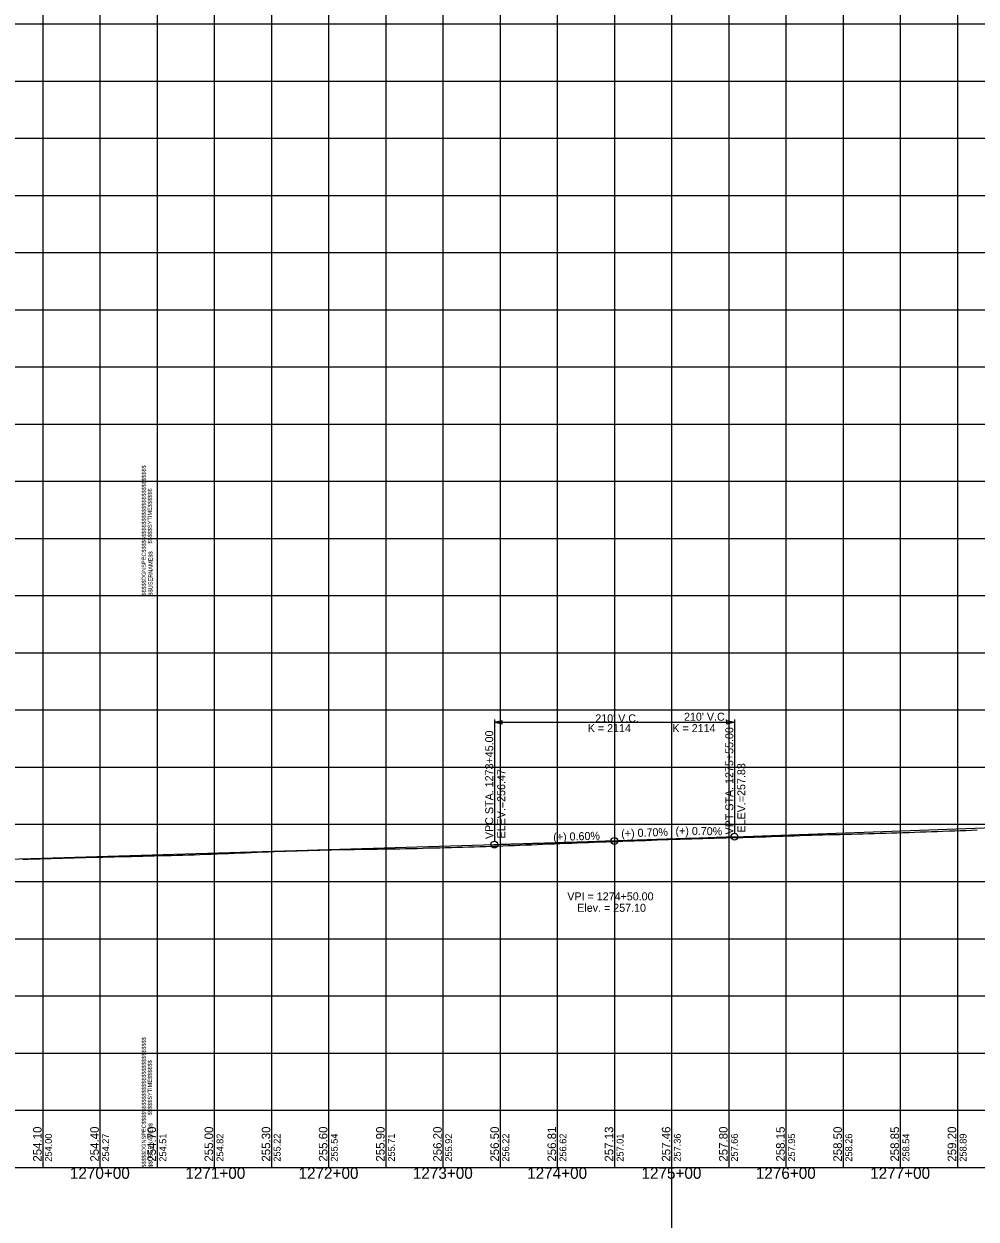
# Model space of a CAD drawing. Extents: x -90830 to 2015517, y -20856 to 836331.
# Drawn here: x 15857 to 16690, y -19432 to -18387 of the extents above; entities that cross this region are included whole.
import ezdxf

# ---------------------------------------------------------------- set-up
doc = ezdxf.new("R2010")
doc.units = 0
for name, color, linetype in [('Level 1', 7, 'Continuous'), ('RD_DDB_GradeTX', 7, 'Continuous'), ('RD_DDB_Profile_Elev', 7, 'Continuous'), ('RD_DDB_Profile_EX', 7, 'Continuous'), ('RD_DDB_Profile_Lbl', 7, 'Continuous'), ('RD_DDB_Profile_PR', 7, 'Continuous'), ('RD_DDB_StaTX', 7, 'Continuous'), ('RD_DDB_StripGrade', 7, 'Continuous'), ('RD_DDB_VCLbl', 7, 'Continuous'), ('RD_GPK_Profile_Cell', 7, 'Continuous'), ('RD_TX_Drainage', 7, 'Continuous')]:
    doc.layers.add(name, color=color, linetype=linetype)

msp = doc.modelspace()

# ---------------------------------------------------------------- linework, layer by layer
at = {"layer": 'Level 1'}
for p, q in [((16423.5, -12693.4), (16423.5, -20856.1)), ((15873.5, -17886.5), (15873.5, -18386.5)), ((15923.5, -17886.5), (15923.5, -18386.5)), ((15973.5, -17886.5), (15973.5, -18386.5)), ((15973.5, -17886.5), (15973.5, -18386.5)), ((15973.5, -17886.5), (15973.5, -18386.5)), ((16023.5, -17886.5), (16023.5, -18386.5)), ((16073.5, -17886.5), (16073.5, -18386.5)), ((16123.5, -17886.5), (16123.5, -18386.5)), ((16173.5, -17886.5), (16173.5, -18386.5)), ((16223.5, -17886.5), (16223.5, -18386.5)), ((16273.5, -17886.5), (16273.5, -18386.5)), ((16323.5, -17886.5), (16323.5, -18386.5)), ((16373.5, -17886.5), (16373.5, -18386.5)), ((16423.5, -17886.5), (16423.5, -18386.5)), ((16473.5, -17886.5), (16473.5, -18386.5)), ((16523.5, -17886.5), (16523.5, -18386.5)), ((16573.5, -17886.5), (16573.5, -18386.5)), ((16623.5, -17886.5), (16623.5, -18386.5)), ((16673.5, -17886.5), (16673.5, -18386.5)), ((14373.5, -18386.5), (15973.5, -18386.5)), ((14373.5, -18386.5), (15973.5, -18386.5)), ((15873.5, -18386.5), (15873.5, -18886.5)), ((15923.5, -18386.5), (15923.5, -18886.5)), ((15973.5, -18386.5), (15973.5, -18886.5)), ((15973.5, -18386.5), (15973.5, -18886.5)), ((15973.5, -18386.5), (17573.5, -18386.5)), ((15973.5, -18386.5), (15973.5, -18886.5)), ((15973.5, -18386.5), (17573.5, -18386.5)), ((16023.5, -18386.5), (16023.5, -18886.5)), ((16073.5, -18386.5), (16073.5, -18886.5)), ((16123.5, -18386.5), (16123.5, -18886.5)), ((16173.5, -18386.5), (16173.5, -18886.5)), ((16223.5, -18386.5), (16223.5, -18886.5)), ((16273.5, -18386.5), (16273.5, -18886.5)), ((16323.5, -18386.5), (16323.5, -18886.5)), ((16373.5, -18386.5), (16373.5, -18886.5)), ((16423.5, -18386.5), (16423.5, -18886.5)), ((16473.5, -18386.5), (16473.5, -18886.5)), ((16523.5, -18386.5), (16523.5, -18886.5)), ((16573.5, -18386.5), (16573.5, -18886.5)), ((16623.5, -18386.5), (16623.5, -18886.5)), ((16673.5, -18386.5), (16673.5, -18886.5)), ((14373.5, -18436.5), (15973.5, -18436.5)), ((15973.5, -18436.5), (17573.5, -18436.5)), ((14373.5, -18486.5), (15973.5, -18486.5)), ((15973.5, -18486.5), (17573.5, -18486.5)), ((14373.5, -18536.5), (15973.5, -18536.5)), ((15973.5, -18536.5), (17573.5, -18536.5)), ((14373.5, -18586.5), (15973.5, -18586.5)), ((15973.5, -18586.5), (17573.5, -18586.5)), ((14373.5, -18636.5), (15973.5, -18636.5)), ((15973.5, -18636.5), (17573.5, -18636.5)), ((14373.5, -18686.5), (15973.5, -18686.5)), ((15973.5, -18686.5), (17573.5, -18686.5)), ((14373.5, -18736.5), (15973.5, -18736.5)), ((15973.5, -18736.5), (17573.5, -18736.5)), ((14373.5, -18786.5), (15973.5, -18786.5)), ((15973.5, -18786.5), (17573.5, -18786.5)), ((14373.5, -18836.5), (15973.5, -18836.5)), ((15973.5, -18836.5), (17573.5, -18836.5)), ((14373.5, -18886.5), (15973.5, -18886.5)), ((14373.5, -18886.5), (15973.5, -18886.5)), ((15873.5, -18886.5), (15873.5, -19386.5)), ((15923.5, -18886.5), (15923.5, -19386.5)), ((15973.5, -18886.5), (17573.5, -18886.5)), ((15973.5, -18886.5), (15973.5, -19386.5)), ((15973.5, -18886.5), (15973.5, -19386.5)), ((15973.5, -18886.5), (17573.5, -18886.5)), ((15973.5, -18886.5), (15973.5, -19386.5)), ((16023.5, -18886.5), (16023.5, -19386.5)), ((16073.5, -18886.5), (16073.5, -19386.5)), ((16123.5, -18886.5), (16123.5, -19386.5)), ((16173.5, -18886.5), (16173.5, -19386.5)), ((16223.5, -18886.5), (16223.5, -19386.5)), ((16273.5, -18886.5), (16273.5, -19386.5)), ((16323.5, -18886.5), (16323.5, -19386.5)), ((16373.5, -18886.5), (16373.5, -19386.5)), ((16423.5, -18886.5), (16423.5, -19386.5)), ((16473.5, -18886.5), (16473.5, -19386.5)), ((16523.5, -18886.5), (16523.5, -19386.5)), ((16573.5, -18886.5), (16573.5, -19386.5)), ((16623.5, -18886.5), (16623.5, -19386.5)), ((16673.5, -18886.5), (16673.5, -19386.5)), ((14373.5, -18936.5), (15973.5, -18936.5)), ((15973.5, -18936.5), (17573.5, -18936.5)), ((14373.5, -18986.5), (15973.5, -18986.5)), ((15973.5, -18986.5), (17573.5, -18986.5)), ((14373.5, -19036.5), (15973.5, -19036.5)), ((15973.5, -19036.5), (17573.5, -19036.5)), ((14373.5, -19086.5), (15973.5, -19086.5)), ((15973.5, -19086.5), (17573.5, -19086.5)), ((14373.5, -19136.5), (15973.5, -19136.5)), ((15973.5, -19136.5), (17573.5, -19136.5)), ((14373.5, -19186.5), (15973.5, -19186.5)), ((15973.5, -19186.5), (17573.5, -19186.5)), ((14373.5, -19236.5), (15973.5, -19236.5)), ((15973.5, -19236.5), (17573.5, -19236.5)), ((14373.5, -19286.5), (15973.5, -19286.5)), ((15973.5, -19286.5), (17573.5, -19286.5)), ((14373.5, -19336.5), (15973.5, -19336.5)), ((15973.5, -19336.5), (17573.5, -19336.5)), ((14373.5, -19386.5), (15973.5, -19386.5)), ((15973.5, -19386.5), (17573.5, -19386.5))]:
    msp.add_line(p, q, dxfattribs=at)
at = {"layer": 'RD_DDB_GradeTX'}
for p, q in [((16302.5, -19103.1), (16370.5, -19101.1)), ((16444.4, -19098.5), (16376.5, -19100.9))]:
    msp.add_line(p, q, dxfattribs=at)
msp.add_circle((16373.5, -19101), 3, dxfattribs=at)
at = {"layer": 'RD_DDB_Profile_EX'}
for points in [[(16045.9, -19111.5), (16050.9, -19111.3), (16055.9, -19111.1), (16060.9, -19110.9), (16065.9, -19110.7), (16070.9, -19110.5), (16075.9, -19110.3), (16080.9, -19110.1), (16085.9, -19110), (16090.9, -19109.8), (16095.9, -19109.6), (16100.9, -19109.5), (16105.9, -19109.3), (16110.9, -19109.2), (16115.9, -19109), (16120.9, -19108.9), (16125.9, -19108.8), (16130.9, -19108.6), (16135.9, -19108.5), (16140.9, -19108.4), (16145.9, -19108.4), (16150.9, -19108.3), (16155.9, -19108.2), (16160.9, -19108.1), (16165.9, -19108.1), (16170.9, -19108), (16175.9, -19107.9), (16180.9, -19107.9), (16185.9, -19107.8), (16190.9, -19107.7), (16195.9, -19107.6), (16200.9, -19107.5), (16205.9, -19107.3), (16210.9, -19107.2), (16215.9, -19107.1), (16220.9, -19107), (16225.9, -19106.8), (16230.9, -19106.7), (16235.9, -19106.6), (16240.9, -19106.5), (16245.9, -19106.3), (16250.9, -19106.2), (16255.9, -19106), (16260.9, -19105.8), (16265.9, -19105.7), (16270.9, -19105.5), (16275.9, -19105.3), (16280.9, -19105.1), (16285.9, -19104.9), (16290.9, -19104.7), (16295.9, -19104.5), (16300.9, -19104.3), (16305.9, -19104.1), (16310.9, -19103.9), (16315.9, -19103.7), (16320.9, -19103.5), (16325.9, -19103.3), (16330.9, -19103.1), (16335.9, -19102.9), (16340.9, -19102.7), (16345.9, -19102.5), (16350.9, -19102.3), (16355.9, -19102.1), (16360.9, -19101.9), (16365.9, -19101.7), (16370.9, -19101.5), (16375.9, -19101.4), (16380.9, -19101.2), (16385.9, -19101), (16390.9, -19100.8), (16395.9, -19100.6), (16400.9, -19100.5), (16405.9, -19100.3), (16410.9, -19100.1), (16415.9, -19099.9), (16420.9, -19099.8), (16425.9, -19099.6), (16430.9, -19099.4), (16435.9, -19099.3), (16440.9, -19099.1), (16445.9, -19098.9), (16450.9, -19098.8), (16455.9, -19098.6), (16460.9, -19098.5), (16465.9, -19098.4), (16470.9, -19098.3), (16475.9, -19098.1), (16480.9, -19098), (16485.9, -19097.9), (16490.9, -19097.8), (16495.9, -19097.6), (16500.9, -19097.5), (16505.9, -19097.3), (16510.9, -19097.2), (16515.9, -19097), (16520.9, -19096.8), (16525.9, -19096.7), (16530.9, -19096.5), (16535.9, -19096.3), (16540.9, -19096.1), (16545.9, -19096)], [(16545.9, -19096), (16550.9, -19095.8), (16555.9, -19095.7), (16560.9, -19095.5), (16565.9, -19095.4), (16570.9, -19095.3), (16575.9, -19095.1), (16580.9, -19095), (16585.9, -19094.8), (16590.9, -19094.7), (16595.9, -19094.6), (16600.9, -19094.4), (16605.9, -19094.3), (16610.9, -19094.2), (16615.9, -19094), (16620.9, -19093.9), (16625.9, -19093.7), (16630.9, -19093.6), (16635.9, -19093.4), (16640.9, -19093.2), (16645.9, -19093.1), (16650.9, -19092.9), (16655.9, -19092.7), (16660.9, -19092.5), (16665.9, -19092.3), (16670.9, -19092.1), (16675.9, -19091.9), (16680.9, -19091.8), (16685.9, -19091.6), (16690.9, -19091.4)], [(15855.9, -19117), (15860.9, -19116.9), (15865.9, -19116.7), (15870.9, -19116.6), (15875.9, -19116.4), (15880.9, -19116.3), (15885.9, -19116.1), (15890.9, -19116), (15895.9, -19115.9), (15900.9, -19115.7), (15905.9, -19115.6), (15910.9, -19115.5), (15915.9, -19115.3), (15920.9, -19115.2), (15925.9, -19115.1), (15930.9, -19115), (15935.9, -19114.8), (15940.9, -19114.7), (15945.9, -19114.6), (15950.9, -19114.5), (15955.9, -19114.4), (15960.9, -19114.3), (15965.9, -19114.2), (15970.9, -19114), (15975.9, -19113.9), (15980.9, -19113.8), (15985.9, -19113.7), (15990.9, -19113.5), (15995.9, -19113.4), (16000.9, -19113.2), (16005.9, -19113.1), (16010.9, -19112.9), (16015.9, -19112.7), (16020.9, -19112.5), (16025.9, -19112.3), (16030.9, -19112.1), (16035.9, -19111.9), (16040.9, -19111.7), (16045.9, -19111.5)]]:
    msp.add_lwpolyline(points, dxfattribs=at)
at = {"layer": 'RD_DDB_Profile_PR'}
for p, q in [((16478.5, -19097.3), (16738.5, -19088.2)), ((15278.5, -19133.9), (16268.5, -19104.2))]:
    msp.add_line(p, q, dxfattribs=at)
msp.add_spline([(16268.5, -19104.2), (16272.7, -19104), (16276.9, -19103.9), (16281.1, -19103.8), (16285.3, -19103.6), (16289.5, -19103.5), (16293.7, -19103.4), (16297.9, -19103.3), (16302.1, -19103.1), (16306.3, -19103), (16310.5, -19102.9), (16314.7, -19102.7), (16318.9, -19102.6), (16323.1, -19102.5), (16327.3, -19102.4), (16331.5, -19102.2), (16335.7, -19102.1), (16339.9, -19102), (16344.1, -19101.8), (16348.3, -19101.7), (16352.5, -19101.6), (16356.7, -19101.4), (16360.9, -19101.3), (16365.1, -19101.1), (16369.3, -19101), (16373.5, -19100.9), (16377.7, -19100.7), (16381.9, -19100.6), (16386.1, -19100.5), (16390.3, -19100.3), (16394.5, -19100.2), (16398.7, -19100), (16402.9, -19099.9), (16407.1, -19099.8), (16411.3, -19099.6), (16415.5, -19099.5), (16419.7, -19099.3), (16423.9, -19099.2), (16428.1, -19099.1), (16432.3, -19098.9), (16436.5, -19098.8), (16440.7, -19098.6), (16444.9, -19098.5), (16449.1, -19098.4), (16453.3, -19098.2), (16457.5, -19098.1), (16461.7, -19097.9), (16465.9, -19097.8), (16470.1, -19097.6), (16474.3, -19097.5), (16478.5, -19097.3)], degree=3, dxfattribs=at)
at = {"layer": 'RD_DDB_VCLbl'}
for p, q in [((16268.5, -18994.8), (16268.5, -19101.2)), ((16268.5, -18997.3), (16478.5, -18997.3)), ((16478.5, -18994.8), (16478.5, -19094.3))]:
    msp.add_line(p, q, dxfattribs=at)
for centre in [(16478.5, -19097.3), (16268.5, -19104.2)]:
    msp.add_circle(centre, 3, dxfattribs=at)
at = {"layer": 'RD_GPK_Profile_Cell'}
msp.add_line((4823.5, -19386.5), (75223.5, -19386.5), dxfattribs=at)
at = {"layer": 'RD_TX_Drainage'}
for points in [[(16275.1, -18999), (16268.5, -18997.3), (16275.1, -18995.7)], [(16471.9, -18995.7), (16478.5, -18997.3), (16471.9, -18999)]]:
    msp.add_lwpolyline(points, close=True, dxfattribs=at)

# ---------------------------------------------------------------- texts
at = {"layer": 'Level 1'}
for s, p in [('$$$$$DGNSPEC$$$$$$$$$$$$$$$$$$$$$$$$$$$$', (15963.6, -18886.6)), ('$$$$$SYTIME$$$$$$', (15968.9, -18841)), ('$$USERNAME$$', (15969.5, -18886.4)), ('$$$$$DGNSPEC$$$$$$$$$$$$$$$$$$$$$$$$$$$$', (15963.6, -19386.6)), ('$$$$$SYTIME$$$$$$', (15968.9, -19341)), ('$$USERNAME$$', (15969.5, -19386.4))]:
    msp.add_text(s, height=3.544, rotation=90, dxfattribs=at).set_placement(p)
at = {"layer": 'RD_DDB_GradeTX'}
for s, rotation, p in [('(+) 0.60%', 1.7184, (16320.1, -19101.1)), ('(+) 0.70%', 2.0027, (16379.6, -19098)), ('(+) 0.70%', 359.0138, (16426.9, -19095.5))]:
    msp.add_text(s, height=7, rotation=rotation, dxfattribs=at).set_placement(p)
at = {"layer": 'RD_DDB_Profile_Elev'}
for s, p in [('254.10', (15872.5, -19381.5)), ('254.40', (15922.5, -19381.5)), ('254.70', (15972.5, -19381.5)), ('255.00', (16022.5, -19381.5)), ('255.30', (16072.5, -19381.5)), ('255.60', (16122.5, -19381.5)), ('255.90', (16172.5, -19381.5)), ('256.20', (16222.5, -19381.5)), ('256.50', (16272.5, -19381.5)), ('256.81', (16322.5, -19381.5)), ('257.13', (16372.5, -19381.5)), ('257.46', (16422.5, -19381.5)), ('257.80', (16472.5, -19381.5)), ('258.15', (16522.5, -19381.5)), ('258.50', (16572.5, -19381.5)), ('258.85', (16622.5, -19381.5)), ('259.20', (16672.5, -19381.5))]:
    msp.add_text(s, height=7.5, rotation=90, dxfattribs=at).set_placement(p)
at = {"layer": 'RD_DDB_Profile_Lbl'}
for s, p in [('VPI = 1274+50.00', (16332.3, -19153)), ('Elev. = 257.10', (16341, -19163))]:
    msp.add_text(s, height=7, dxfattribs=at).set_placement(p)
at = {"layer": 'RD_DDB_StaTX'}
for s, p in [('1270+00', (15897.2, -19396.5)), ('1271+00', (15998.2, -19396.5)), ('1272+00', (16097.2, -19396.5)), ('1273+00', (16197.2, -19396.5)), ('1274+00', (16297.2, -19396.5)), ('1275+00', (16397.2, -19396.5)), ('1276+00', (16497.2, -19396.5)), ('1277+00', (16597.2, -19396.5))]:
    msp.add_text(s, height=10, dxfattribs=at).set_placement(p)
at = {"layer": 'RD_DDB_StripGrade'}
for s, height, p in [('VPT STA. 1275+55.00 ', 7, (16477.5, -19095.4)), ('VPC STA. 1273+45.00 ', 7, (16267.5, -19099.4)), ('ELEV.=257.83', 7, (16488, -19093.7)), ('ELEV.=256.47', 7, (16278, -19098.9)), ('254.00', 6, (15881.5, -19381.5)), ('254.27', 6, (15931.5, -19381.5)), ('254.51', 6, (15981.5, -19381.5)), ('254.82', 6, (16031.5, -19381.5)), ('255.22', 6, (16081.5, -19381.5)), ('255.54', 6, (16131.5, -19381.5)), ('255.71', 6, (16181.5, -19381.5)), ('255.92', 6, (16231.5, -19381.5)), ('256.22', 6, (16281.5, -19381.5)), ('256.62', 6, (16331.5, -19381.5)), ('257.01', 6, (16381.5, -19381.5)), ('257.36', 6, (16431.5, -19381.5)), ('257.66', 6, (16481.5, -19381.5)), ('257.95', 6, (16531.5, -19381.5)), ('258.26', 6, (16581.5, -19381.5)), ('258.54', 6, (16631.5, -19381.5)), ('258.89', 6, (16681.5, -19381.5))]:
    msp.add_text(s, height=height, rotation=90, dxfattribs=at).set_placement(p)
at = {"layer": 'RD_DDB_VCLbl'}
for s, p in [("210' V.C.", (16356.8, -18997.3)), ("210' V.C.", (16434.4, -18995.9)), ('K = 2114', (16350.2, -19005.9)), ('K = 2114', (16424.2, -19005.9))]:
    msp.add_text(s, height=7, dxfattribs=at).set_placement(p)

doc.saveas('drawing.dxf')
